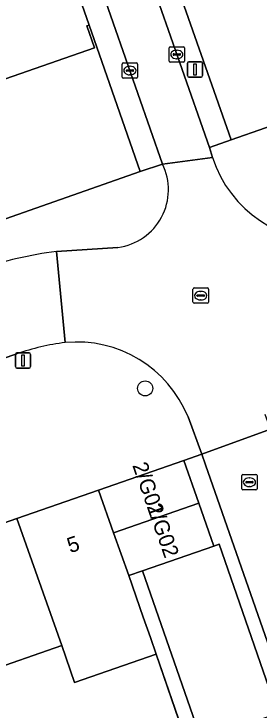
# Model space of a CAD drawing. Extents: x 159371 to 159986, y 382987 to 383597.
# Drawn here: x 159635.1 to 159651.04, y 383270.05 to 383315.4 of the extents above; entities that cross this region are included whole.
import ezdxf

# ---------------------------------------------------------------- set-up
doc = ezdxf.new("R2010")
doc.units = 0
for name, color, linetype in [('IMGEO_Boom', 7, 'Continuous'), ('IMGEO_Erf', 7, 'Continuous'), ('IMGEO_Kolk', 7, 'Continuous'), ('IMGEO_Lichtmast', 7, 'Continuous'), ('IMGEO_Muur', 7, 'Continuous'), ('IMGEO_Pand', 7, 'Continuous'), ('IMGEO_Pand_nummerreeks', 7, 'Continuous'), ('IMGEO_Parkeervlak_open', 7, 'Continuous'), ('IMGEO_Rijbaan_lokaal_open', 7, 'Continuous'), ('IMGEO_Rioolput', 7, 'Continuous'), ('IMGEO_Voetpad_open', 7, 'Continuous')]:
    doc.layers.add(name, color=color, linetype=linetype)

msp = doc.modelspace()

# ---------------------------------------------------------------- linework, layer by layer
at = {"layer": 'IMGEO_Boom'}
msp.add_circle((159643.634, 383291.001), 0.489, dxfattribs=at)
at = {"layer": 'IMGEO_Erf'}
for points in [[(159633.525, 383310.811), (159640.34, 383313.197), (159639.844, 383314.612), (159639.998, 383314.666), (159638.001, 383320.394), (159611.994, 383311.273)], [(159635.047, 383262.869), (159637.708, 383263.577), (159636.837, 383266.271), (159640.593, 383267.486), (159644.321, 383268.692), (159645.192, 383265.998), (159646.802, 383266.554), (159644.346, 383273.697), (159639.045, 383271.847), (159638.205, 383274.255), (159633.097, 383272.473)]]:
    msp.add_lwpolyline(points, dxfattribs=at)
at = {"layer": 'IMGEO_Kolk'}
for p, q in [((159645.192, 383312.328), (159645.192, 383313.18)), ((159645.267, 383313.254), (159646.119, 383313.254)), ((159645.68, 383313.034), (159645.705, 383313.034)), ((159646.193, 383313.18), (159646.193, 383312.328)), ((159645.451, 383312.748), (159645.451, 383312.76)), ((159645.889, 383312.711), (159645.491, 383312.711)), ((159645.494, 383312.797), (159645.892, 383312.797)), ((159645.703, 383312.474), (159645.678, 383312.474)), ((159645.935, 383312.76), (159645.935, 383312.748)), ((159642.138, 383311.282), (159642.138, 383312.134)), ((159642.213, 383312.208), (159643.065, 383312.208)), ((159642.626, 383311.988), (159642.651, 383311.988)), ((159643.139, 383312.134), (159643.139, 383311.282)), ((159646.119, 383312.254), (159645.267, 383312.254)), ((159642.397, 383311.702), (159642.397, 383311.714)), ((159642.835, 383311.665), (159642.437, 383311.665)), ((159642.44, 383311.751), (159642.838, 383311.751)), ((159642.881, 383311.714), (159642.881, 383311.702)), ((159643.065, 383311.208), (159642.213, 383311.208)), ((159642.649, 383311.428), (159642.624, 383311.428)), ((159649.912, 383284.465), (159649.912, 383285.317)), ((159649.987, 383285.391), (159650.839, 383285.391)), ((159650.913, 383285.317), (159650.913, 383284.465)), ((159650.171, 383284.885), (159650.171, 383284.897)), ((159650.609, 383284.848), (159650.211, 383284.848)), ((159650.214, 383284.934), (159650.612, 383284.934)), ((159650.4, 383285.171), (159650.425, 383285.171)), ((159650.655, 383284.897), (159650.655, 383284.885)), ((159650.839, 383284.391), (159649.987, 383284.391)), ((159650.423, 383284.611), (159650.398, 383284.611))]:
    msp.add_line(p, q, dxfattribs=at)
for points in [[(159645.192, 383312.328), (159645.192, 383313.18)], [(159645.267, 383313.254), (159646.119, 383313.254)], [(159646.193, 383313.18), (159646.193, 383312.328)], [(159642.138, 383311.282), (159642.138, 383312.134)], [(159642.213, 383312.208), (159643.065, 383312.208)], [(159643.139, 383312.134), (159643.139, 383311.282)], [(159646.119, 383312.254), (159645.267, 383312.254)], [(159643.065, 383311.208), (159642.213, 383311.208)], [(159649.912, 383284.465), (159649.912, 383285.317)], [(159649.987, 383285.391), (159650.839, 383285.391)], [(159650.913, 383285.317), (159650.913, 383284.465)], [(159650.839, 383284.391), (159649.987, 383284.391)]]:
    msp.add_lwpolyline(points, dxfattribs=at)
for centre, radius, start, end in [((159645.269, 383313.178), 0.0765, 91.552, 178.448), ((159645.269, 383313.178), 0.0765, 91.552, 178.448), ((159646.117, 383313.178), 0.0765, 1.552, 88.448), ((159646.117, 383313.178), 0.0765, 1.552, 88.448), ((159645.491, 383312.757), 0.0403, 85.8775, 175.7526), ((159645.488, 383312.747), 0.0366, 178.938, 274.7102), ((159645.892, 383312.754), 0.043, 264.8664, 352.4533), ((159645.896, 383312.759), 0.0386, 1.7309, 96.639), ((159642.215, 383312.132), 0.0765, 91.552, 178.448), ((159642.215, 383312.132), 0.0765, 91.552, 178.448), ((159643.063, 383312.132), 0.0765, 1.552, 88.448), ((159643.063, 383312.132), 0.0765, 1.552, 88.448), ((159645.269, 383312.33), 0.0765, 181.552, 268.448), ((159645.269, 383312.33), 0.0765, 181.552, 268.448), ((159646.117, 383312.33), 0.0765, 271.552, 358.448), ((159646.117, 383312.33), 0.0765, 271.552, 358.448), ((159642.437, 383311.711), 0.0403, 85.8775, 175.7526), ((159642.434, 383311.701), 0.0366, 178.938, 274.7102), ((159642.838, 383311.708), 0.043, 264.8664, 352.4533), ((159642.842, 383311.713), 0.0386, 1.7309, 96.639), ((159642.215, 383311.284), 0.0765, 181.552, 268.448), ((159642.215, 383311.284), 0.0765, 181.552, 268.448), ((159643.063, 383311.284), 0.0765, 271.552, 358.448), ((159643.063, 383311.284), 0.0765, 271.552, 358.448), ((159649.989, 383285.315), 0.0765, 91.552, 178.448), ((159649.989, 383285.315), 0.0765, 91.552, 178.448), ((159650.837, 383285.315), 0.0765, 1.552, 88.448), ((159650.837, 383285.315), 0.0765, 1.552, 88.448), ((159650.211, 383284.894), 0.0403, 85.8775, 175.7526), ((159650.208, 383284.884), 0.0366, 178.938, 274.7102), ((159650.612, 383284.891), 0.043, 264.8664, 352.4533), ((159650.616, 383284.896), 0.0386, 1.7309, 96.639), ((159649.989, 383284.467), 0.0765, 181.552, 268.448), ((159649.989, 383284.467), 0.0765, 181.552, 268.448), ((159650.837, 383284.467), 0.0765, 271.552, 358.448), ((159650.837, 383284.467), 0.0765, 271.552, 358.448)]:
    msp.add_arc(centre, radius, start, end, dxfattribs=at)
for centre, major_axis, ratio, start_param, end_param in [((159645.679, 383312.754), (-0.387, 0.002), 0.722429, 4.712389, 7.853982), ((159645.704, 383312.754), (-0.39, 0.002), 0.717154, 1.570796, 4.712389), ((159642.625, 383311.708), (-0.387, 0.002), 0.722429, 4.712389, 7.853982), ((159642.65, 383311.708), (-0.39, 0.002), 0.717154, 1.570796, 4.712389), ((159650.399, 383284.891), (-0.387, 0.002), 0.722429, 4.712389, 7.853982), ((159650.424, 383284.891), (-0.39, 0.002), 0.717154, 1.570796, 4.712389)]:
    msp.add_ellipse(centre, major_axis=major_axis, ratio=ratio, start_param=start_param, end_param=end_param, dxfattribs=at)
at = {"layer": 'IMGEO_Lichtmast'}
for p, q in [((159646.382, 383311.379), (159646.382, 383312.179)), ((159646.382, 383312.179), (159646.382, 383311.379)), ((159646.482, 383312.279), (159647.272, 383312.279)), ((159647.272, 383312.279), (159646.482, 383312.279)), ((159647.372, 383312.179), (159647.372, 383311.379)), ((159647.372, 383311.379), (159647.372, 383312.179)), ((159647.272, 383311.279), (159646.482, 383311.279)), ((159646.482, 383311.279), (159647.272, 383311.279)), ((159635.192, 383292.419), (159635.192, 383293.219)), ((159635.192, 383293.219), (159635.192, 383292.419)), ((159635.292, 383293.319), (159636.082, 383293.319)), ((159636.082, 383293.319), (159635.292, 383293.319)), ((159636.182, 383293.219), (159636.182, 383292.419)), ((159636.182, 383292.419), (159636.182, 383293.219)), ((159636.082, 383292.319), (159635.292, 383292.319)), ((159635.292, 383292.319), (159636.082, 383292.319))]:
    msp.add_line(p, q, dxfattribs=at)
for points in [[(159646.802, 383312.154), (159646.952, 383312.154), (159646.952, 383311.404), (159646.802, 383311.404), (159646.802, 383312.154)], [(159635.612, 383293.194), (159635.762, 383293.194), (159635.762, 383292.444), (159635.612, 383292.444), (159635.612, 383293.194)]]:
    msp.add_lwpolyline(points, dxfattribs=at)
for centre, start, end in [((159646.482, 383312.179), 90, 180), ((159646.482, 383312.179), 90, 180), ((159647.272, 383312.179), 0, 90), ((159647.272, 383312.179), 360, 90), ((159646.482, 383311.379), 180, 270), ((159646.482, 383311.379), 180, 270), ((159647.272, 383311.379), 270, 0), ((159647.272, 383311.379), 270, 0), ((159635.292, 383293.219), 90, 180), ((159635.292, 383293.219), 90, 180), ((159636.082, 383293.219), 0, 90), ((159636.082, 383293.219), 360, 90), ((159635.292, 383292.419), 180, 270), ((159635.292, 383292.419), 180, 270), ((159636.082, 383292.419), 270, 0), ((159636.082, 383292.419), 270, 0)]:
    msp.add_arc(centre, 0.1, start, end, dxfattribs=at)
at = {"layer": 'IMGEO_Muur'}
for points in [[(159638.001, 383320.394), (159639.998, 383314.666)], [(159644.346, 383273.697), (159646.813, 383266.522)]]:
    msp.add_lwpolyline(points, dxfattribs=at)
at = {"layer": 'IMGEO_Pand'}
for points in [[(159645.886, 383316.734), (159649.218, 383307.194), (159658.161, 383310.326), (159667.221, 383313.499), (159676.282, 383316.672)], [(159595.048, 383300.613), (159595.555, 383299.1), (159594.186, 383298.625), (159597.511, 383289.099), (159606.384, 383292.204), (159615.509, 383295.398), (159624.57, 383298.569), (159633.726, 383301.773), (159643.318, 383305.13), (159639.998, 383314.666)], [(159639.998, 383314.666), (159639.844, 383314.612), (159640.34, 383313.197), (159633.525, 383310.811)]]:
    msp.add_lwpolyline(points, dxfattribs=at)
for points in [[(159647.125, 383283.52), (159646.153, 383286.308), (159640.596, 383284.369), (159641.574, 383281.6)], [(159642.565, 383278.803), (159641.574, 383281.6), (159640.596, 383284.369), (159635.29, 383282.518), (159638.205, 383274.255), (159639.045, 383271.847), (159644.346, 383273.697), (159643.971, 383274.771), (159643.506, 383276.105)], [(159647.125, 383283.52), (159641.574, 383281.6), (159642.565, 383278.803), (159643.458, 383279.114), (159648.098, 383280.733)], [(159635.29, 383282.518), (159630.183, 383280.737), (159633.097, 383272.473), (159638.205, 383274.255)]]:
    msp.add_lwpolyline(points, close=True, dxfattribs=at)
at = {"layer": 'IMGEO_Parkeervlak_open'}
msp.add_lwpolyline([(159643.458, 383279.114), (159647.245, 383268.195), (159652.26, 383269.832), (159648.437, 383280.851), (159648.098, 383280.733)], close=True, dxfattribs=at)
at = {"layer": 'IMGEO_Rijbaan_lokaal_open'}
for points in [[(159638.165, 383334.29), (159635.142, 383333.243), (159644.757, 383305.615), (159648.011, 383306.048), (159647.812, 383306.694)], [(159647.315, 383286.718), (159647.551, 383286.019), (159654.055, 383267.387), (159653.786, 383267.274), (159659.36, 383250), (159663.852, 383236.075), (159663.364, 383235.901), (159663.772, 383234.65), (159668.65, 383236.234), (159668.26, 383237.434), (159669.446, 383237.835), (159665.513, 383250), (159658.393, 383272.015), (159657.725, 383271.809), (159652.205, 383287.893), (159652.017, 383288.429), (159651.778, 383288.352)]]:
    msp.add_lwpolyline(points, close=True, dxfattribs=at)
for points in [[(159648.011, 383306.048), (159644.757, 383305.615)], [(159641.866, 383300.19), (159637.866, 383299.924), (159638.436, 383293.989)], [(159638.436, 383293.989), (159637.866, 383299.924)], [(159588.61, 383276.954), (159595.694, 383279.416), (159595.831, 383279.464), (159630.111, 383291.458), (159634.336, 383292.929), (159635.287, 383293.248)], [(159646.422, 383289.143), (159647.315, 383286.718), (159651.778, 383288.352), (159651.438, 383289.296)]]:
    msp.add_lwpolyline(points, dxfattribs=at)
for centre, radius, start, end in [((159655.509, 383308.461), 7.877, 197.8383, 274.5442), ((159641.366, 383303.939), 3.782, 277.592, 26.3014), ((159640.998, 383275.303), 24.82, 97.2488, 109.2056), ((159640.106, 383279.829), 14.258, 96.7276, 109.7554), ((159639.178, 383286.208), 7.816, 22.0545, 95.4458)]:
    msp.add_arc(centre, radius, start, end, dxfattribs=at)
at = {"layer": 'IMGEO_Rioolput'}
for p, q in [((159646.744, 383296.619), (159646.744, 383297.471)), ((159646.819, 383297.545), (159647.671, 383297.545)), ((159647.745, 383297.471), (159647.745, 383296.619)), ((159647.003, 383297.039), (159647.003, 383297.051)), ((159647.441, 383297.002), (159647.043, 383297.002)), ((159647.046, 383297.088), (159647.444, 383297.088)), ((159647.232, 383297.325), (159647.257, 383297.325)), ((159647.487, 383297.051), (159647.487, 383297.039)), ((159647.255, 383296.765), (159647.23, 383296.765)), ((159647.671, 383296.545), (159646.819, 383296.545))]:
    msp.add_line(p, q, dxfattribs=at)
for points in [[(159646.744, 383296.619), (159646.744, 383297.471)], [(159646.819, 383297.545), (159647.671, 383297.545)], [(159647.745, 383297.471), (159647.745, 383296.619)], [(159647.671, 383296.545), (159646.819, 383296.545)]]:
    msp.add_lwpolyline(points, dxfattribs=at)
for centre, radius, start, end in [((159646.821, 383297.469), 0.0765, 91.552, 178.448), ((159646.821, 383297.469), 0.0765, 91.552, 178.448), ((159647.669, 383297.469), 0.0765, 1.552, 88.448), ((159647.669, 383297.469), 0.0765, 1.552, 88.448), ((159647.043, 383297.048), 0.0403, 85.8775, 175.7526), ((159647.04, 383297.038), 0.0366, 178.938, 274.7102), ((159647.444, 383297.045), 0.043, 264.8664, 352.4533), ((159647.448, 383297.05), 0.0386, 1.7309, 96.639), ((159646.821, 383296.621), 0.0765, 181.552, 268.448), ((159646.821, 383296.621), 0.0765, 181.552, 268.448), ((159647.669, 383296.621), 0.0765, 271.552, 358.448), ((159647.669, 383296.621), 0.0765, 271.552, 358.448)]:
    msp.add_arc(centre, radius, start, end, dxfattribs=at)
for centre, major_axis, ratio, start_param, end_param in [((159647.231, 383297.045), (-0.387, 0.002), 0.722429, 4.712389, 7.853982), ((159647.256, 383297.045), (-0.39, 0.002), 0.717154, 1.570796, 4.712389)]:
    msp.add_ellipse(centre, major_axis=major_axis, ratio=ratio, start_param=start_param, end_param=end_param, dxfattribs=at)
at = {"layer": 'IMGEO_Voetpad_open'}
for points in [[(159645.886, 383316.734), (159643.966, 383322.174), (159643.889, 383322.392), (159643.399, 383323.78), (159639.534, 383334.943), (159638.685, 383334.47), (159638.165, 383334.29), (159647.812, 383306.694), (159649.218, 383307.194)], [(159635.142, 383333.243), (159634.69, 383333.087), (159633.682, 383332.842), (159635.65, 383327.182), (159637.605, 383321.561), (159612.758, 383312.821), (159610.898, 383318.498), (159609.052, 383324.122), (159607.877, 383323.724), (159609.788, 383317.937), (159611.905, 383311.499), (159611.994, 383311.273), (159638.001, 383320.394), (159639.998, 383314.666), (159643.318, 383305.13), (159644.757, 383305.615)]]:
    msp.add_lwpolyline(points, close=True, dxfattribs=at)
for points in [[(159700.197, 383323.784), (159698.94, 383324.722), (159695.046, 383323.244), (159685.437, 383319.879), (159676.282, 383316.672), (159667.221, 383313.499), (159658.161, 383310.326), (159649.218, 383307.194), (159647.812, 383306.694), (159648.011, 383306.048)], [(159644.757, 383305.615), (159643.318, 383305.13), (159633.726, 383301.773), (159624.57, 383298.569), (159615.509, 383295.398), (159606.384, 383292.204), (159597.511, 383289.099), (159597.121, 383288.896), (159598.195, 383286.558), (159601.874, 383287.839), (159632.833, 383298.741)], [(159637.866, 383299.924), (159641.866, 383300.19)], [(159635.287, 383293.248), (159634.336, 383292.929), (159630.111, 383291.458)], [(159602.593, 383272.92), (159619.419, 383278.79), (159619.644, 383278.868), (159620.206, 383277.256), (159625.085, 383278.958), (159630.183, 383280.737), (159635.29, 383282.518), (159640.596, 383284.369), (159646.153, 383286.308), (159647.315, 383286.718), (159646.422, 383289.143)], [(159654.055, 383267.387), (159647.551, 383286.019), (159647.315, 383286.718), (159646.153, 383286.308), (159647.125, 383283.52), (159648.098, 383280.733), (159648.437, 383280.851), (159652.26, 383269.832)], [(159647.245, 383268.195), (159643.458, 383279.114), (159642.565, 383278.803), (159643.506, 383276.105), (159643.971, 383274.771), (159644.346, 383273.697), (159646.802, 383266.554)]]:
    msp.add_lwpolyline(points, dxfattribs=at)
for centre, radius, start, end in [((159655.509, 383308.461), 7.877, 197.8383, 274.5442), ((159641.366, 383303.939), 3.782, 277.592, 26.3014), ((159640.998, 383275.303), 24.82, 97.2488, 109.2056), ((159640.106, 383279.829), 14.258, 96.7276, 109.7554), ((159639.178, 383286.208), 7.816, 22.0545, 95.4458)]:
    msp.add_arc(centre, radius, start, end, dxfattribs=at)

# ---------------------------------------------------------------- texts
at = {"layer": 'IMGEO_Pand_nummerreeks'}
for s, rotation, p in [('2/G01', 289.2328, (159642.788, 383285.994)), ('2/G02', 289.2328, (159643.723, 383283.317)), ('5', 19.2313, (159638.763, 383280.256))]:
    msp.add_text(s, height=1, rotation=rotation, dxfattribs=at).set_placement(p)

doc.saveas('drawing.dxf')
